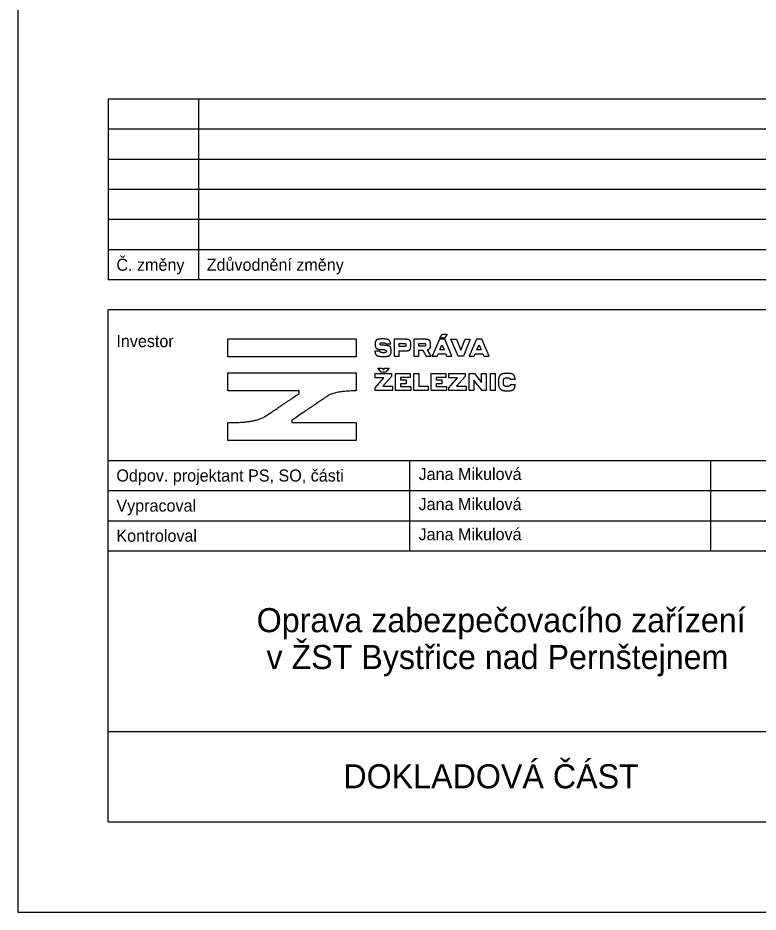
# Model space of a CAD drawing. Extents: x -790471 to -790261, y -990806 to -990509.
# Drawn here: x -790470.6 to -790347.7, y -990805.6 to -990657.1 of the extents above; entities that cross this region are included whole.
import ezdxf

# ---------------------------------------------------------------- set-up
doc = ezdxf.new("R2010")
doc.units = 0
for name, color, linetype in [('logo_sprava_zeleznic', 7, 'Continuous'), ('Ramečky', 7, 'Continuous'), ('Rámečky-tisk', 7, 'Continuous'), ('Text', 7, 'Continuous'), ('Text barevný', 7, 'Continuous')]:
    doc.layers.add(name, color=color, linetype=linetype)

msp = doc.modelspace()

# ---------------------------------------------------------------- linework, layer by layer
at = {"layer": 'logo_sprava_zeleznic'}
for p, q in [((-790400.56, -990710.22), (-790400.12, -990709.55)), ((-790399.78, -990710.22), (-790400.56, -990710.22)), ((-790400.12, -990709.55), (-790399.3, -990709.55)), ((-790399.3, -990709.55), (-790399.78, -990710.22)), ((-790409.76, -990711.43), (-790410.15, -990711.4)), ((-790409.51, -990711.19), (-790408.69, -990711.19)), ((-790398.7, -990710.43), (-790397.76, -990710.43)), ((-790397.49, -990713.24), (-790398.7, -990710.43)), ((-790397.76, -990710.43), (-790397.05, -990712.24)), ((-790397.05, -990712.24), (-790396.34, -990710.43)), ((-790395.49, -990710.43), (-790396.64, -990713.24)), ((-790396.34, -990710.43), (-790395.49, -990710.43)), ((-790410.51, -990712.4), (-790411.36, -990712.4)), ((-790396.64, -990713.24), (-790397.49, -990713.24)), ((-790411.26, -990716.13), (-790408.55, -990716.13)), ((-790411.26, -990716.82), (-790411.26, -990716.13)), ((-790410.29, -990715.91), (-790410.83, -990715.24)), ((-790410.83, -990715.24), (-790410.14, -990715.24)), ((-790409.53, -990715.91), (-790410.29, -990715.91)), ((-790410.14, -990715.24), (-790409.91, -990715.52)), ((-790409.91, -990715.52), (-790409.68, -990715.24)), ((-790409.68, -990715.24), (-790408.97, -990715.24)), ((-790408.97, -990715.24), (-790409.53, -990715.91)), ((-790408.55, -990716.13), (-790408.55, -990716.58)), ((-790407.92, -990716.13), (-790405.49, -990716.13)), ((-790407.92, -990718.94), (-790407.92, -990716.13)), ((-790405.49, -990716.13), (-790405.49, -990716.78)), ((-790404.86, -990716.13), (-790404.05, -990716.13)), ((-790404.86, -990718.94), (-790404.86, -990716.13)), ((-790404.05, -990716.13), (-790404.05, -990718.24)), ((-790401.99, -990716.13), (-790399.57, -990716.13)), ((-790401.99, -990718.94), (-790401.99, -990716.13)), ((-790399.57, -990716.13), (-790399.57, -990716.78)), ((-790399.03, -990716.13), (-790396.33, -990716.13)), ((-790399.03, -990716.82), (-790399.03, -990716.13)), ((-790396.33, -990716.13), (-790396.33, -990716.58)), ((-790395.69, -990716.13), (-790394.78, -990716.13)), ((-790395.69, -990718.94), (-790395.69, -990716.13)), ((-790394.78, -990716.13), (-790393.63, -990717.63)), ((-790393.63, -990717.63), (-790393.63, -990716.13)), ((-790393.63, -990716.13), (-790392.85, -990716.13)), ((-790392.85, -990716.13), (-790392.85, -990718.94)), ((-790411.3, -990718.48), (-790409.84, -990716.82)), ((-790409.84, -990716.82), (-790411.26, -990716.82)), ((-790408.55, -990716.58), (-790410.02, -990718.24)), ((-790405.49, -990716.78), (-790407.1, -990716.78)), ((-790407.1, -990716.78), (-790407.1, -990717.15)), ((-790407.1, -990717.15), (-790406.14, -990717.15)), ((-790406.14, -990717.15), (-790406.14, -990717.82)), ((-790399.57, -990716.78), (-790401.18, -990716.78)), ((-790401.18, -990716.78), (-790401.18, -990717.15)), ((-790401.18, -990717.15), (-790400.22, -990717.15)), ((-790400.22, -990717.15), (-790400.22, -990717.82)), ((-790399.07, -990718.48), (-790397.61, -990716.82)), ((-790397.61, -990716.82), (-790399.03, -990716.82)), ((-790396.33, -990716.58), (-790397.8, -990718.24)), ((-790393.53, -990718.94), (-790394.89, -990717.21)), ((-790394.89, -990717.21), (-790394.89, -990718.94)), ((-790388.84, -990717.07), (-790388.01, -990717.07)), ((-790411.3, -990718.94), (-790411.3, -990718.48)), ((-790408.39, -990718.94), (-790411.3, -990718.94)), ((-790410.02, -990718.24), (-790408.39, -990718.24)), ((-790408.39, -990718.24), (-790408.39, -990718.94)), ((-790405.34, -990718.94), (-790407.92, -990718.94)), ((-790406.14, -990717.82), (-790407.1, -990717.82)), ((-790407.1, -990717.82), (-790407.1, -990718.25)), ((-790407.1, -990718.25), (-790405.34, -990718.25)), ((-790405.34, -990718.25), (-790405.34, -990718.94)), ((-790402.47, -990718.94), (-790404.86, -990718.94)), ((-790404.05, -990718.24), (-790402.47, -990718.24)), ((-790402.47, -990718.24), (-790402.47, -990718.94)), ((-790399.41, -990718.94), (-790401.99, -990718.94)), ((-790400.22, -990717.82), (-790401.18, -990717.82)), ((-790401.18, -990717.82), (-790401.18, -990718.25)), ((-790401.18, -990718.25), (-790399.41, -990718.25)), ((-790399.41, -990718.25), (-790399.41, -990718.94)), ((-790399.07, -990718.94), (-790399.07, -990718.48)), ((-790396.16, -990718.94), (-790399.07, -990718.94)), ((-790397.8, -990718.24), (-790396.16, -990718.24)), ((-790396.16, -990718.24), (-790396.16, -990718.94)), ((-790394.89, -990718.94), (-790395.69, -990718.94)), ((-790392.85, -990718.94), (-790393.53, -990718.94)), ((-790388.01, -990718), (-790388.83, -990718))]:
    msp.add_line(p, q, dxfattribs=at)
for points in [[(-790435.73, -990710.36), (-790414.41, -990710.36), (-790414.41, -990713.33), (-790435.73, -990713.33)], [(-790401.8, -990713.24), (-790400.98, -990713.24), (-790400.82, -990712.85), (-790399.57, -990712.85), (-790399.41, -990713.24), (-790398.53, -990713.24), (-790399.73, -990710.43), (-790400.6, -990710.43)], [(-790400.19, -990711.34), (-790399.85, -990712.18), (-790400.54, -990712.18)], [(-790395.65, -990713.24), (-790394.83, -990713.24), (-790394.66, -990712.85), (-790393.42, -990712.85), (-790393.26, -990713.24), (-790392.38, -990713.24), (-790393.57, -990710.43), (-790394.45, -990710.43)], [(-790394.04, -990711.34), (-790393.7, -990712.18), (-790394.39, -990712.18)], [(-790392.16, -990716.13), (-790391.35, -990716.13), (-790391.35, -990718.94), (-790392.16, -990718.94)]]:
    msp.add_lwpolyline(points, close=True, dxfattribs=at)
for points in [[(-790406.38, -990710.43), (-790408.11, -990710.43), (-790408.11, -990713.24), (-790407.3, -990713.24), (-790407.3, -990712.34), (-790406.38, -990712.34)], [(-790406.48, -990711.64), (-790407.3, -990711.64), (-790407.3, -990711.13), (-790406.48, -990711.13)], [(-790403.12, -990710.43), (-790404.84, -990710.43), (-790404.84, -990713.24), (-790404.03, -990713.24), (-790404.03, -990712.26), (-790403.39, -990712.26), (-790402.84, -990713.24), (-790401.98, -990713.24), (-790402.59, -990712.17)], [(-790403.22, -990711.59), (-790404.03, -990711.59), (-790404.03, -990711.11), (-790403.22, -990711.11)], [(-790423.87, -990719.41), (-790423.87, -990719), (-790435.73, -990719), (-790435.73, -990716.02), (-790414.41, -990716.02), (-790414.41, -990719)], [(-790425.1, -990723.86), (-790425.1, -990724.27), (-790414.41, -990724.27), (-790414.41, -990727.25), (-790435.73, -990727.25), (-790435.73, -990724.27), (-790435.71, -990724.27)]]:
    msp.add_lwpolyline(points, dxfattribs=at)
for centre, radius, start, end in [((-790411.9, -990733.09), 21.01, 84.2634, 85.3384), ((-790461.18, -990666.56), 64.69, 304.0901, 305.2133), ((-790124.63, -991160.5), 530.02, 124.292, 124.5333)]:
    msp.add_arc(centre, radius, start, end, dxfattribs=at)
for points in [[(-790410.05, -990710.37), (-790410.77, -990710.37), (-790411.29, -990710.66), (-790411.29, -990711.24)], [(-790411.29, -990711.24), (-790411.29, -990711.78), (-790410.87, -990712.09), (-790410.19, -990712.15)], [(-790410.46, -990711.2), (-790410.46, -990711.07), (-790410.3, -990711.01), (-790410.05, -990711.01)], [(-790410.15, -990711.4), (-790410.35, -990711.38), (-790410.46, -990711.32), (-790410.46, -990711.2)], [(-790408.69, -990711.19), (-790408.77, -990710.82), (-790409.09, -990710.37), (-790410.05, -990710.37)], [(-790410.05, -990711.01), (-790409.73, -990711.01), (-790409.55, -990711.12), (-790409.51, -990711.19)], [(-790408.63, -990712.36), (-790408.63, -990711.74), (-790409.03, -990711.49), (-790409.76, -990711.43)], [(-790406.48, -990711.13), (-790406.27, -990711.13), (-790406.17, -990711.21), (-790406.17, -990711.38)], [(-790406.17, -990711.38), (-790406.17, -990711.55), (-790406.27, -990711.64), (-790406.48, -990711.64)], [(-790405.34, -990711.38), (-790405.34, -990710.75), (-790405.73, -990710.43), (-790406.38, -990710.43)], [(-790406.38, -990712.34), (-790405.73, -990712.34), (-790405.34, -990712.01), (-790405.34, -990711.38)], [(-790403.22, -990711.11), (-790403.02, -990711.11), (-790402.91, -990711.19), (-790402.91, -990711.35)], [(-790402.91, -990711.35), (-790402.91, -990711.51), (-790403.02, -990711.59), (-790403.22, -990711.59)], [(-790402.08, -990711.36), (-790402.08, -990710.75), (-790402.49, -990710.43), (-790403.12, -990710.43)], [(-790402.59, -990712.17), (-790402.27, -990712.03), (-790402.08, -990711.75), (-790402.08, -990711.36)], [(-790411.36, -990712.4), (-790411.29, -990712.79), (-790410.93, -990713.29), (-790409.92, -990713.29)], [(-790409.92, -990712.66), (-790410.28, -990712.66), (-790410.46, -990712.52), (-790410.51, -990712.4)], [(-790409.92, -990713.29), (-790409.08, -990713.29), (-790408.63, -990712.96), (-790408.63, -990712.36)], [(-790409.47, -990712.42), (-790409.47, -990712.57), (-790409.6, -990712.66), (-790409.92, -990712.66)], [(-790409.8, -990712.19), (-790409.6, -990712.21), (-790409.47, -990712.26), (-790409.47, -990712.42)], [(-790389.36, -990716.08), (-790390.22, -990716.08), (-790390.82, -990716.69), (-790390.82, -990717.53)], [(-790388.01, -990717.07), (-790388.06, -990716.75), (-790388.4, -990716.08), (-790389.36, -990716.08)], [(-790390.82, -990717.53), (-790390.82, -990718.38), (-790390.22, -990718.99), (-790389.36, -990718.99)], [(-790390, -990717.53), (-790390, -990717.13), (-790389.76, -990716.81), (-790389.36, -990716.81)], [(-790389.36, -990718.26), (-790389.76, -990718.26), (-790390, -990717.94), (-790390, -990717.53)], [(-790389.36, -990716.81), (-790389.02, -990716.81), (-790388.88, -990717), (-790388.84, -990717.07)], [(-790414.41, -990719), (-790417.9, -990719), (-790420.38, -990720.67), (-790423.25, -990722.6)], [(-790389.36, -990718.99), (-790388.37, -990718.99), (-790388.05, -990718.26), (-790388.01, -990718)], [(-790388.83, -990718), (-790388.87, -990718.07), (-790389.02, -990718.26), (-790389.36, -990718.26)], [(-790435.71, -990724.27), (-790431.06, -990724.26), (-790428.08, -990722.26), (-790424.92, -990720.13)]]:
    msp.add_open_spline(points, degree=2, dxfattribs=at)
at = {"layer": 'Ramečky'}
for p, q in [((-790275.59, -990670.55), (-790455.59, -990670.55)), ((-790455.59, -990670.55), (-790455.59, -990700.55)), ((-790440.59, -990670.55), (-790440.59, -990700.55)), ((-790305.59, -990675.55), (-790455.59, -990675.55)), ((-790305.59, -990680.55), (-790455.59, -990680.55)), ((-790305.59, -990685.55), (-790455.59, -990685.55)), ((-790305.59, -990690.55), (-790455.59, -990690.55)), ((-790305.59, -990695.55), (-790455.59, -990695.55)), ((-790275.59, -990700.55), (-790455.59, -990700.55)), ((-790275.59, -990705.55), (-790455.59, -990705.55)), ((-790455.59, -990790.55), (-790455.59, -990705.55)), ((-790455.59, -990730.55), (-790325.59, -990730.55)), ((-790455.59, -990735.55), (-790325.59, -990735.55)), ((-790455.59, -990740.55), (-790325.59, -990740.55)), ((-790455.59, -990745.55), (-790325.59, -990745.55)), ((-790455.59, -990775.55), (-790275.59, -990775.55)), ((-790455.59, -990790.55), (-790275.59, -990790.55))]:
    msp.add_line(p, q, dxfattribs=at)
for points in [[(-790405.59, -990730.55), (-790405.59, -990745.55)], [(-790355.59, -990730.55), (-790355.59, -990745.55)]]:
    msp.add_lwpolyline(points, dxfattribs=at)
at = {"layer": 'Rámečky-tisk'}
msp.add_line((-790470.59, -990508.55), (-790470.59, -990805.55), dxfattribs=at)
msp.add_lwpolyline([(-790470.59, -990805.55), (-790260.59, -990805.55), (-790260.59, -990508.55)], dxfattribs=at)

# ---------------------------------------------------------------- texts
at = {"layer": 'Text'}
for s, p in [('Č. změny', (-790454.24, -990699.05)), ('Zdůvodnění změny', (-790439.24, -990699.05)), ('Investor', (-790454.24, -990711.73)), ('Odpov. projektant PS, SO, části', (-790454.24, -990734.05)), ('Jana Mikulová ', (-790404.07, -990733.8)), ('Vypracoval', (-790454.24, -990739.05)), ('Jana Mikulová ', (-790404.07, -990738.8)), ('Kontroloval', (-790454.24, -990744.05)), ('Jana Mikulová ', (-790404.07, -990743.8))]:
    msp.add_text(s, height=2, dxfattribs=at).set_placement(p)
at = {"layer": 'Text barevný'}
for s, p in [('Oprava zabezpečovacího zařízení', (-790430.95, -990759.07)), ('v ŽST Bystřice nad Pernštejnem', (-790429.33, -990765.19)), ('DOKLADOVÁ ČÁST', (-790416.56, -990785))]:
    msp.add_text(s, height=4, dxfattribs=at).set_placement(p)

doc.saveas('drawing.dxf')
